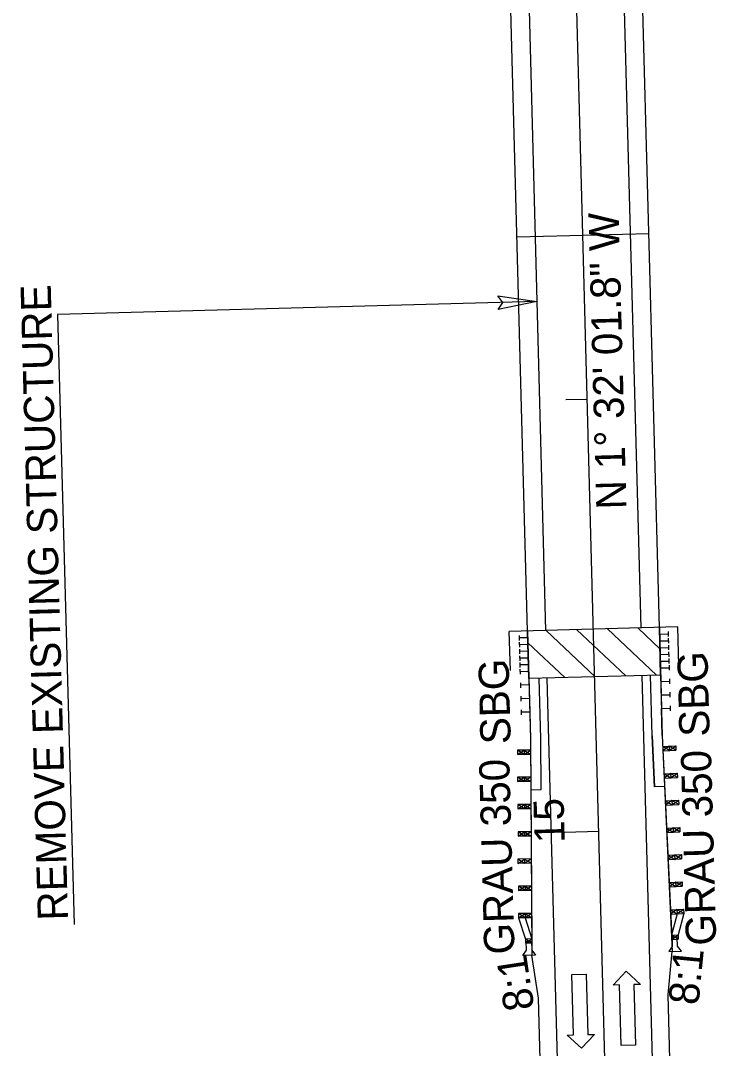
# Model space of a CAD drawing. Extents: x 1835351 to 1836442, y 993887 to 995358.
# Drawn here: x 1835756.1 to 1835917.2, y 994407.3 to 994645.1 of the extents above; entities that cross this region are included whole.
import ezdxf

# ---------------------------------------------------------------- set-up
doc = ezdxf.new("R2010")
doc.units = 0
for name, color, linetype in [('Prop Approach Slab', 7, 'Continuous'), ('Prop Approach Slab Hatching', 7, 'Continuous'), ('Prop Dimension', 7, 'Continuous'), ('Prop Dimension Text', 7, 'Continuous'), ('Prop EOT', 7, 'Continuous'), ('Prop Guardrail', 7, 'Continuous'), ('Prop Guardrail Anchor Unit CELL', 7, 'Continuous'), ('Prop Horizontal Alignment', 7, 'Continuous'), ('Prop Horizontal Alignment Direction Label', 7, 'Continuous'), ('Prop Horizontal Alignment Tick Label', 7, 'Continuous'), ('Prop Horizontal Alignment Tick Large', 7, 'Continuous'), ('Prop Horizontal Alignment Tick Small', 7, 'Continuous'), ('Prop Lane Arrow CELL', 7, 'Continuous'), ('Prop Paved Shoulder', 7, 'Continuous'), ('Prop Roadway Bridge', 7, 'Continuous'), ('Prop SBG', 7, 'Continuous'), ('Prop Structure Anchor Unit CELL', 7, 'Continuous'), ('Prop Terminator CELL', 7, 'Continuous')]:
    doc.layers.add(name, color=color, linetype=linetype)

msp = doc.modelspace()

# ---------------------------------------------------------------- linework, layer by layer
at = {"layer": 'Prop Approach Slab'}
for p, q in [((1835873.74, 994492.91), (1835873.45, 994503.9)), ((1835904.23, 994493.72), (1835903.94, 994504.72)), ((1835904.23, 994493.72), (1835873.74, 994492.91))]:
    msp.add_line(p, q, dxfattribs=at)
at = {"layer": 'Prop Approach Slab Hatching'}
for p, q in [((1835877.78, 994504.02), (1835889.1, 994493.32)), ((1835884.86, 994504.21), (1835896.18, 994493.51)), ((1835891.94, 994504.4), (1835903.26, 994493.7)), ((1835899.02, 994504.59), (1835904.07, 994499.81)), ((1835873.52, 994501.16), (1835882.03, 994493.13))]:
    msp.add_line(p, q, dxfattribs=at)
at = {"layer": 'Prop Dimension'}
for p, q in [((1835875.61, 994580.12), (1835764.64, 994577.09)), ((1835764.64, 994577.09), (1835768.5, 994436.03))]:
    msp.add_line(p, q, dxfattribs=at)
at = {"layer": 'Prop EOT'}
for p, q in [((1835881.63, 994357.26), (1835877.99, 994493.02)), ((1835903.62, 994357.85), (1835899.98, 994493.61))]:
    msp.add_line(p, q, dxfattribs=at)
at = {"layer": 'Prop Guardrail'}
msp.add_line((1835873.95, 994485.16), (1835874.12, 994478.91), dxfattribs=at)
msp.add_lwpolyline([(1835904.61, 994479.73), (1835904.44, 994485.97)], dxfattribs=at)
at = {"layer": 'Prop Guardrail Anchor Unit CELL'}
for p, q in [((1835904.61, 994479.73), (1835906.79, 994433.03)), ((1835874.12, 994478.91), (1835874.43, 994432.16)), ((1835904.73, 994477.19), (1835907.72, 994477.33)), ((1835906.27, 994476.26), (1835907.72, 994477.33)), ((1835907.72, 994477.33), (1835907.77, 994476.33)), ((1835874.13, 994476.37), (1835871.14, 994476.35)), ((1835871.14, 994475.35), (1835872.63, 994476.36)), ((1835872.64, 994475.36), (1835871.14, 994476.35)), ((1835871.14, 994476.35), (1835871.14, 994475.35)), ((1835874.14, 994475.37), (1835871.14, 994475.35)), ((1835872.63, 994476.36), (1835872.64, 994475.36)), ((1835872.63, 994476.36), (1835874.14, 994475.37)), ((1835872.64, 994475.36), (1835874.13, 994476.37)), ((1835874.14, 994475.37), (1835872.64, 994475.36)), ((1835874.13, 994476.37), (1835874.14, 994475.37)), ((1835904.73, 994477.19), (1835904.77, 994476.19)), ((1835906.27, 994476.26), (1835904.73, 994477.19)), ((1835906.22, 994477.26), (1835904.77, 994476.19)), ((1835904.77, 994476.19), (1835907.77, 994476.33)), ((1835904.77, 994476.19), (1835906.27, 994476.26)), ((1835906.22, 994477.26), (1835906.27, 994476.26)), ((1835907.77, 994476.33), (1835906.22, 994477.26)), ((1835905.02, 994470.89), (1835908.07, 994471.04)), ((1835905.02, 994470.89), (1835906.59, 994469.96)), ((1835906.54, 994470.96), (1835905.07, 994469.89)), ((1835906.54, 994470.96), (1835906.59, 994469.96)), ((1835908.12, 994470.04), (1835906.54, 994470.96)), ((1835906.59, 994469.96), (1835908.07, 994471.04)), ((1835908.07, 994471.04), (1835908.12, 994470.04)), ((1835874.18, 994470.07), (1835871.12, 994470.05)), ((1835872.66, 994469.06), (1835871.12, 994470.05)), ((1835871.12, 994470.05), (1835871.13, 994469.05)), ((1835871.13, 994469.05), (1835872.65, 994470.06)), ((1835874.18, 994469.07), (1835871.13, 994469.05)), ((1835872.65, 994470.06), (1835872.66, 994469.06)), ((1835872.65, 994470.06), (1835874.18, 994469.07)), ((1835874.18, 994470.07), (1835872.66, 994469.06)), ((1835905.07, 994469.89), (1835908.12, 994470.04)), ((1835874.22, 994463.77), (1835871.17, 994463.75)), ((1835872.7, 994462.75), (1835871.17, 994463.75)), ((1835871.17, 994463.75), (1835871.18, 994462.75)), ((1835871.18, 994462.75), (1835872.7, 994463.76)), ((1835874.22, 994463.77), (1835872.7, 994462.75)), ((1835872.7, 994463.76), (1835872.7, 994462.75)), ((1835872.7, 994463.76), (1835874.23, 994462.77)), ((1835905.31, 994464.6), (1835908.36, 994464.74)), ((1835905.31, 994464.6), (1835906.88, 994463.67)), ((1835906.84, 994464.67), (1835905.36, 994463.6)), ((1835905.36, 994463.6), (1835908.41, 994463.74)), ((1835906.84, 994464.67), (1835906.88, 994463.67)), ((1835908.41, 994463.74), (1835906.84, 994464.67)), ((1835906.88, 994463.67), (1835908.36, 994464.74)), ((1835908.36, 994464.74), (1835908.41, 994463.74)), ((1835874.23, 994462.77), (1835871.18, 994462.75)), ((1835905.61, 994458.3), (1835908.64, 994458.45)), ((1835905.61, 994458.3), (1835905.66, 994457.31)), ((1835905.61, 994458.3), (1835907.17, 994457.38)), ((1835907.13, 994458.37), (1835905.66, 994457.31)), ((1835907.13, 994458.37), (1835907.17, 994457.38)), ((1835908.69, 994457.45), (1835907.13, 994458.37)), ((1835907.17, 994457.38), (1835908.64, 994458.45)), ((1835908.64, 994458.45), (1835908.69, 994457.45)), ((1835874.26, 994457.46), (1835871.23, 994457.44)), ((1835871.23, 994456.44), (1835872.74, 994457.45)), ((1835872.75, 994456.45), (1835871.23, 994457.44)), ((1835871.23, 994457.44), (1835871.23, 994456.44)), ((1835874.27, 994456.46), (1835871.23, 994456.44)), ((1835872.74, 994457.45), (1835872.75, 994456.45)), ((1835872.74, 994457.45), (1835874.27, 994456.46)), ((1835874.26, 994457.46), (1835872.75, 994456.45)), ((1835874.26, 994457.46), (1835874.27, 994456.46)), ((1835905.66, 994457.31), (1835908.69, 994457.45)), ((1835874.31, 994451.16), (1835871.17, 994451.14)), ((1835871.17, 994450.14), (1835872.74, 994451.15)), ((1835872.74, 994450.15), (1835871.17, 994451.14)), ((1835871.17, 994451.14), (1835871.17, 994450.14)), ((1835874.31, 994451.16), (1835872.74, 994450.15)), ((1835872.74, 994451.15), (1835872.74, 994450.15)), ((1835872.74, 994451.15), (1835874.31, 994450.16)), ((1835905.9, 994452.01), (1835909.04, 994452.16)), ((1835905.9, 994452.01), (1835907.52, 994451.08)), ((1835907.47, 994452.08), (1835905.95, 994451.01)), ((1835905.95, 994451.01), (1835909.08, 994451.16)), ((1835907.47, 994452.08), (1835907.52, 994451.08)), ((1835909.08, 994451.16), (1835907.47, 994452.08)), ((1835907.52, 994451.08), (1835909.04, 994452.16)), ((1835909.04, 994452.16), (1835909.08, 994451.16)), ((1835874.31, 994450.16), (1835871.17, 994450.14)), ((1835874.35, 994444.86), (1835871.35, 994444.84)), ((1835872.85, 994443.85), (1835871.35, 994444.84)), ((1835871.35, 994444.84), (1835871.36, 994443.84)), ((1835871.36, 994443.84), (1835872.85, 994444.85)), ((1835874.35, 994444.86), (1835872.85, 994443.85)), ((1835872.85, 994444.85), (1835872.85, 994443.85)), ((1835872.85, 994444.85), (1835874.35, 994443.86)), ((1835906.2, 994445.72), (1835909.19, 994445.86)), ((1835906.2, 994445.72), (1835907.74, 994444.79)), ((1835907.7, 994445.79), (1835906.25, 994444.72)), ((1835906.25, 994444.72), (1835909.24, 994444.86)), ((1835907.7, 994445.79), (1835907.74, 994444.79)), ((1835909.24, 994444.86), (1835907.7, 994445.79)), ((1835907.74, 994444.79), (1835909.19, 994445.86)), ((1835909.19, 994445.86), (1835909.24, 994444.86)), ((1835874.35, 994443.86), (1835871.36, 994443.84)), ((1835906.49, 994439.42), (1835909.55, 994439.56)), ((1835906.49, 994439.42), (1835908.07, 994438.49)), ((1835908.02, 994439.49), (1835906.54, 994438.42)), ((1835908.02, 994439.49), (1835908.07, 994438.49)), ((1835909.6, 994438.56), (1835908.02, 994439.49)), ((1835908.07, 994438.49), (1835909.55, 994439.56)), ((1835909.55, 994439.56), (1835909.6, 994438.56)), ((1835874.39, 994438.56), (1835871.33, 994438.54)), ((1835871.33, 994437.54), (1835872.86, 994438.55)), ((1835872.87, 994437.55), (1835871.33, 994438.54)), ((1835871.33, 994438.54), (1835871.33, 994437.54)), ((1835874.4, 994437.56), (1835871.33, 994437.54)), ((1835871.33, 994437.54), (1835872.93, 994432.65)), ((1835872.86, 994438.55), (1835872.87, 994437.55)), ((1835872.86, 994438.55), (1835874.4, 994437.56)), ((1835874.39, 994438.56), (1835872.87, 994437.55)), ((1835872.87, 994437.55), (1835874.43, 994432.66)), ((1835906.54, 994438.42), (1835909.6, 994438.56)), ((1835908.07, 994438.49), (1835906.77, 994433.53)), ((1835909.6, 994438.56), (1835908.27, 994433.6)), ((1835874.43, 994432.66), (1835872.93, 994432.65)), ((1835872.93, 994432.65), (1835872.93, 994432.15)), ((1835874.44, 994431.66), (1835872.93, 994432.65)), ((1835872.93, 994432.65), (1835872.94, 994431.65)), ((1835872.94, 994431.65), (1835874.43, 994432.66)), ((1835873.14, 994432.1), (1835873.75, 994432.11)), ((1835873.75, 994432.11), (1835874.36, 994432.13)), ((1835874.36, 994432.13), (1835874.41, 994430.08)), ((1835906.77, 994433.53), (1835908.27, 994433.6)), ((1835908.31, 994432.6), (1835906.77, 994433.53)), ((1835906.82, 994432.53), (1835908.27, 994433.6)), ((1835906.82, 994432.53), (1835908.31, 994432.6)), ((1835907.48, 994433.02), (1835906.87, 994433)), ((1835906.87, 994433), (1835906.93, 994430.95)), ((1835908.09, 994433.03), (1835907.48, 994433.02)), ((1835908.15, 994430.99), (1835908.09, 994433.03)), ((1835908.27, 994433.6), (1835908.29, 994433.1)), ((1835908.27, 994433.6), (1835908.31, 994432.6)), ((1835872.36, 994428.85), (1835873.19, 994430.05)), ((1835874.44, 994431.66), (1835872.94, 994431.65)), ((1835873.19, 994430.05), (1835873.14, 994432.1)), ((1835874.41, 994430.08), (1835875.3, 994428.93)), ((1835906.93, 994430.95), (1835906.1, 994429.75)), ((1835906.1, 994429.75), (1835909.04, 994429.83)), ((1835909.04, 994429.83), (1835908.15, 994430.99)), ((1835875.3, 994428.93), (1835872.36, 994428.85))]:
    msp.add_line(p, q, dxfattribs=at)
at = {"layer": 'Prop Horizontal Alignment'}
msp.add_line((1835893.09, 994340.01), (1835881.78, 994762.31), dxfattribs=at)
at = {"layer": 'Prop Horizontal Alignment Tick Large'}
msp.add_line((1835889.95, 994457.52), (1835881.95, 994457.3), dxfattribs=at)
at = {"layer": 'Prop Horizontal Alignment Tick Small'}
msp.add_line((1835887.27, 994557.48), (1835882.27, 994557.35), dxfattribs=at)
at = {"layer": 'Prop Lane Arrow CELL'}
for p, q in [((1835893.25, 994421.99), (1835896.26, 994425.22)), ((1835896.26, 994425.22), (1835899.55, 994422.16)), ((1835883.72, 994424.45), (1835887.02, 994424.54)), ((1835884.1, 994410.46), (1835883.72, 994424.45)), ((1835887.02, 994424.54), (1835887.4, 994410.55)), ((1835894.75, 994422.03), (1835893.25, 994421.99)), ((1835895.13, 994408.03), (1835894.75, 994422.03)), ((1835899.55, 994422.16), (1835898.05, 994422.12)), ((1835898.05, 994422.12), (1835898.43, 994408.12)), ((1835882.6, 994410.42), (1835884.1, 994410.46)), ((1835885.89, 994407.36), (1835882.6, 994410.42)), ((1835888.9, 994410.59), (1835885.89, 994407.36)), ((1835887.4, 994410.55), (1835888.9, 994410.59)), ((1835898.43, 994408.12), (1835895.13, 994408.03))]:
    msp.add_line(p, q, dxfattribs=at)
at = {"layer": 'Prop Paved Shoulder'}
for p, q in [((1835873.74, 994492.91), (1835874.12, 994478.91)), ((1835904.23, 994493.72), (1835904.61, 994479.73)), ((1835904.61, 994479.73), (1835906.94, 994429.78)), ((1835874.12, 994478.91), (1835874.46, 994428.91)), ((1835902.28, 994479.62), (1835902.83, 994467.86)), ((1835905.16, 994467.93), (1835902.83, 994467.86)), ((1835876.53, 994467.16), (1835874.2, 994467.1)), ((1835905.96, 994419.75), (1835906.94, 994429.78)), ((1835875.97, 994418.95), (1835874.46, 994428.91)), ((1835877.63, 994357.15), (1835875.97, 994418.95)), ((1835907.62, 994357.95), (1835905.96, 994419.75))]:
    msp.add_line(p, q, dxfattribs=at)
at = {"layer": 'Prop Roadway Bridge'}
for p, q in [((1835873.45, 994503.9), (1835868.3, 994696.21)), ((1835877.7, 994504.02), (1835872.55, 994696.33)), ((1835899.69, 994504.6), (1835894.54, 994696.92)), ((1835903.94, 994504.72), (1835898.79, 994697.03)), ((1835871.01, 994595.06), (1835901.5, 994595.88)), ((1835908.19, 994504.83), (1835869.2, 994503.79)), ((1835869.45, 994494.79), (1835869.2, 994503.79)), ((1835908.43, 994495.84), (1835908.19, 994504.83))]:
    msp.add_line(p, q, dxfattribs=at)
at = {"layer": 'Prop SBG'}
for p, q in [((1835876.07, 994492.97), (1835876.45, 994478.93)), ((1835902.28, 994479.62), (1835901.9, 994493.66)), ((1835876.45, 994478.93), (1835876.53, 994467.16)), ((1835902.83, 994467.86), (1835902.28, 994479.62))]:
    msp.add_line(p, q, dxfattribs=at)
at = {"layer": 'Prop Structure Anchor Unit CELL'}
for p, q in [((1835873.45, 994503.9), (1835873.95, 994485.16)), ((1835903.94, 994504.72), (1835904.44, 994485.97)), ((1835905.96, 994503.78), (1835905.99, 994502.64)), ((1835871.48, 994502.86), (1835871.51, 994501.71)), ((1835873.49, 994502.34), (1835871.49, 994502.29)), ((1835871.52, 994501.3), (1835871.55, 994500.15)), ((1835903.98, 994503.16), (1835905.98, 994503.21)), ((1835904.02, 994501.59), (1835906.02, 994501.65)), ((1835906.01, 994502.22), (1835906.04, 994501.08)), ((1835873.53, 994500.78), (1835871.53, 994500.72)), ((1835871.56, 994499.73), (1835871.59, 994498.59)), ((1835873.57, 994499.22), (1835871.57, 994499.16)), ((1835904.06, 994500.03), (1835906.06, 994500.09)), ((1835906.05, 994500.66), (1835906.08, 994499.51)), ((1835906.09, 994499.1), (1835906.12, 994497.95)), ((1835871.6, 994498.17), (1835871.63, 994497.03)), ((1835873.62, 994497.65), (1835871.62, 994497.6)), ((1835871.64, 994496.61), (1835871.67, 994495.47)), ((1835904.1, 994498.47), (1835906.1, 994498.52)), ((1835904.15, 994496.91), (1835906.15, 994496.96)), ((1835906.13, 994497.53), (1835906.16, 994496.39)), ((1835873.66, 994496.09), (1835871.66, 994496.04)), ((1835871.68, 994495.05), (1835871.72, 994493.9)), ((1835873.7, 994494.53), (1835871.7, 994494.48)), ((1835904.19, 994495.35), (1835906.19, 994495.4)), ((1835906.17, 994495.97), (1835906.2, 994494.83)), ((1835871.77, 994491.93), (1835871.8, 994490.78)), ((1835904.27, 994492.22), (1835906.27, 994492.28)), ((1835906.26, 994492.85), (1835906.29, 994491.7)), ((1835873.78, 994491.41), (1835871.78, 994491.35)), ((1835906.34, 994489.72), (1835906.37, 994488.58)), ((1835871.85, 994488.8), (1835871.88, 994487.66)), ((1835873.87, 994488.28), (1835871.87, 994488.23)), ((1835904.36, 994489.1), (1835906.35, 994489.15)), ((1835871.94, 994485.68), (1835871.97, 994484.53)), ((1835873.95, 994485.16), (1835871.95, 994485.1)), ((1835904.44, 994485.97), (1835906.44, 994486.03)), ((1835906.42, 994486.6), (1835906.45, 994485.46))]:
    msp.add_line(p, q, dxfattribs=at)
at = {"layer": 'Prop Terminator CELL'}
msp.add_lwpolyline([(1835866.57, 994581.42), (1835875.61, 994580.12), (1835866.6, 994578.27), (1835867.71, 994579.9)], close=True, dxfattribs=at)

# ---------------------------------------------------------------- texts
at = {"layer": 'Prop Dimension Text'}
msp.add_text('REMOVE EXISTING STRUCTURE', height=7, rotation=91.5643, dxfattribs=at).set_placement((1835767.1, 994437.02))
at = {"layer": 'Prop Guardrail Anchor Unit CELL'}
for p in [(1835917.12, 994431.22), (1835870.43, 994429.16)]:
    msp.add_text('GRAU 350', height=7, rotation=91.5643, dxfattribs=at).set_placement(p)
at = {"layer": 'Prop Horizontal Alignment Direction Label'}
msp.add_text('N 1%%d 32\' 01.8" W', height=7, rotation=91.5338, dxfattribs=at).set_placement((1835896.35, 994532.11))
at = {"layer": 'Prop Horizontal Alignment Tick Label'}
msp.add_text('15', height=7, rotation=91.5338, dxfattribs=at).set_placement((1835882.05, 994454.92))
at = {"layer": 'Prop Terminator CELL'}
for s, rotation, p in [('SBG', 91.5338, (1835869.56, 994477.8)), ('SBG', 91.5338, (1835915.59, 994479.53)), ('8:1', 84.4074, (1835912.97, 994417.21)), ('8:1', 98.6603, (1835875.03, 994416.59))]:
    msp.add_text(s, height=7, rotation=rotation, dxfattribs=at).set_placement(p)

doc.saveas('drawing.dxf')
